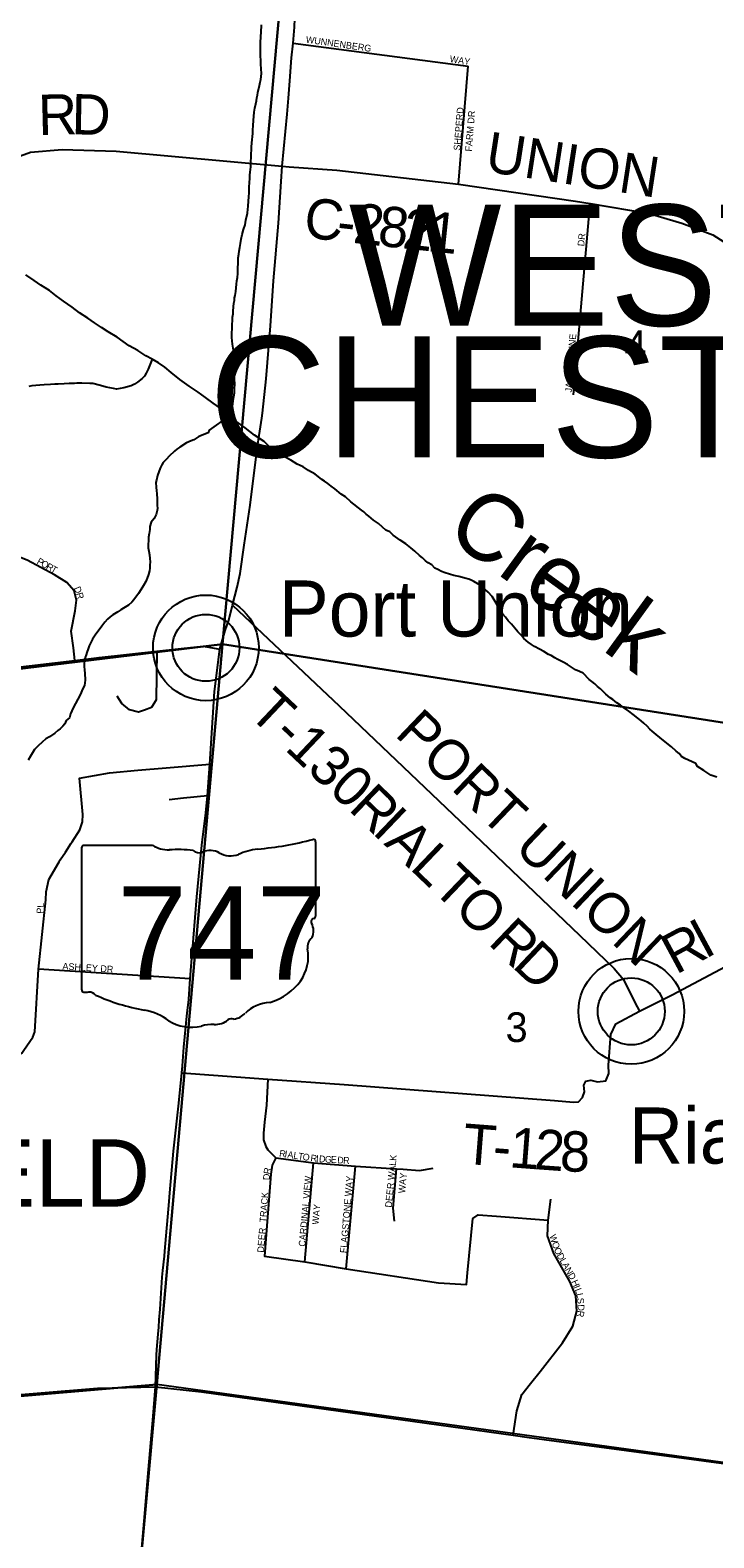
# Model space of a CAD drawing. Extents: x 1310247 to 1552180, y 377264 to 706493.
# Drawn here: x 1411903 to 1416988, y 484836 to 496050 of the extents above; entities that cross this region are included whole.
import ezdxf

# ---------------------------------------------------------------- set-up
doc = ezdxf.new("R2010")
doc.units = 0
for name, color, linetype in [('GM_X_City_Street', 7, 'Continuous'), ('GM_X_Corporation_Text', 7, 'Continuous'), ('GM_X_County_Road', 7, 'Continuous'), ('GM_X_County_Road_Text', 7, 'Continuous'), ('GM_X_Minor_River', 7, 'Continuous'), ('GM_X_Minor_River_Text', 7, 'Continuous'), ('GM_X_Section', 7, 'Continuous'), ('GM_X_Section_Text', 7, 'Continuous'), ('GM_X_State_Location', 7, 'Continuous'), ('GM_X_State_Route', 7, 'Continuous'), ('GM_X_State_Shield', 7, 'Continuous'), ('GM_X_Township_Road', 7, 'Continuous'), ('GM_X_Township_Road_Text', 7, 'Continuous'), ('GM_X_Township_Subdivision', 7, 'Continuous'), ('GM_X_Township_Subdivision_Text', 7, 'Continuous'), ('GM_X_Township_Text', 7, 'Continuous'), ('GM_X_Unincorporated', 7, 'Continuous'), ('GM_X_Unincorporated_Location', 7, 'Continuous'), ('GM_X_Unincorporated_Text', 7, 'Continuous')]:
    doc.layers.add(name, color=color, linetype=linetype)

msp = doc.modelspace()

# ---------------------------------------------------------------- linework, layer by layer
at = {"layer": 'GM_X_City_Street'}
msp.add_lwpolyline([(1413223, 490355), (1413043, 490337), (1412937, 490325)], dxfattribs=at)
at = {"layer": 'GM_X_County_Road'}
for points in [[(1408246, 494848), (1408977, 494429), (1409293, 494228), (1409610, 494093), (1409847, 494050), (1410120, 494057), (1410438, 494136), (1410670, 494255), (1410986, 494506), (1411392, 494848), (1411515, 494951), (1411672, 495059), (1411906, 495143), (1412141, 495163), (1412543, 495150), (1413777, 495038), (1413829, 495035)], [(1413829, 495035), (1414183, 495010), (1415090, 494905), (1415959, 494778), (1416068, 494762), (1416508, 494687), (1416751, 494616), (1416980, 494527), (1417280, 494338), (1417448, 494199), (1417669, 493954), (1417814, 493796), (1417927, 493690), (1418152, 493540), (1418294, 493471), (1418453, 493416), (1418749, 493371)], [(1407906, 490837), (1407912, 490836), (1408014, 490835), (1408238, 490860), (1408358, 490885), (1409402, 491011), (1410363, 491131), (1411747, 491305), (1412235, 491361), (1412416, 491385), (1412846, 491432), (1413026, 491451), (1413191, 491468), (1413313, 491445)], [(1408962, 485642), (1409118, 485655), (1409242, 485672), (1409576, 485698), (1410045, 485742), (1410812, 485814), (1411055, 485838), (1412404, 485949), (1412836, 485959)], [(1412836, 485959), (1413178, 485923), (1415496, 485599), (1415614, 485583), (1415727, 485567), (1417527, 485328), (1418095, 485240)]]:
    msp.add_lwpolyline(points, dxfattribs=at)
at = {"layer": 'GM_X_Minor_River'}
for points in [[(1413539, 494993), (1413544, 495035), (1413544, 495065), (1413547, 495111), (1413549, 495181), (1413551, 495213), (1413559, 495283), (1413559, 495308), (1413562, 495340), (1413565, 495380), (1413567, 495408), (1413570, 495440), (1413574, 495470), (1413581, 495502), (1413586, 495526), (1413590, 495548), (1413594, 495566), (1413597, 495586), (1413610, 495640), (1413614, 495664), (1413619, 495684), (1413624, 495728), (1413622, 495764), (1413619, 495798), (1413618, 495832), (1413616, 495853), (1413617, 495875), (1413616, 495929), (1413616, 495953), (1413619, 496005), (1413620, 496033), (1413623, 496091)], [(1413381, 493179), (1413410, 493268), (1413414, 493294), (1413419, 493326), (1413422, 493354), (1413424, 493376), (1413425, 493425), (1413423, 493449), (1413424, 493481), (1413427, 493509), (1413425, 493539), (1413425, 493611), (1413421, 493642), (1413412, 493686), (1413409, 493714), (1413404, 493764), (1413406, 493863), (1413408, 493889), (1413409, 493915), (1413412, 493941), (1413414, 493963), (1413419, 494021), (1413422, 494039), (1413424, 494059), (1413428, 494077), (1413433, 494107), (1413438, 494161), (1413440, 494185), (1413445, 494211), (1413448, 494240), (1413450, 494356), (1413455, 494384), (1413457, 494406), (1413462, 494434), (1413468, 494464), (1413473, 494496), (1413481, 494530), (1413490, 494568), (1413501, 494602), (1413508, 494638), (1413519, 494688), (1413523, 494720), (1413524, 494740), (1413526, 494780), (1413529, 494808), (1413532, 494844), (1413533, 494880), (1413535, 494920), (1413536, 494945), (1413538, 494973), (1413539, 494993)], [(1413720, 492916), (1413644, 492992), (1413571, 493037), (1413501, 493093), (1413449, 493129), (1413381, 493179), (1413330, 493229), (1413263, 493275), (1413208, 493317), (1413153, 493357), (1413086, 493403), (1413017, 493451), (1412951, 493503), (1412904, 493543), (1412857, 493576), (1412811, 493604), (1412764, 493627), (1412703, 493667), (1412640, 493703), (1412549, 493768), (1412482, 493807), (1412433, 493840), (1412382, 493874), (1412332, 493907), (1412271, 493949), (1412216, 493989), (1412152, 494035), (1412097, 494075), (1412046, 494115), (1411982, 494153), (1411933, 494189), (1411872, 494231)], [(1412811, 493604), (1412781, 493530), (1412766, 493499), (1412753, 493477), (1412737, 493460), (1412702, 493431), (1412679, 493417), (1412655, 493406), (1412628, 493397), (1412600, 493389), (1412572, 493384), (1412546, 493381), (1412522, 493384), (1412496, 493389), (1412468, 493396), (1412444, 493402), (1412416, 493409), (1412370, 493421), (1412348, 493423), (1412288, 493425), (1412250, 493424), (1412232, 493423), (1412194, 493422), (1412156, 493419), (1412111, 493418), (1412087, 493417), (1412055, 493414), (1412007, 493412), (1411975, 493409), (1411946, 493407), (1411916, 493404), (1411892, 493401)], [(1413381, 493179), (1413235, 493075), (1413227, 493055), (1413158, 493029), (1413121, 493004), (1413100, 492997), (1413066, 492980), (1413017, 492949), (1412994, 492934), (1412976, 492918), (1412936, 492881), (1412916, 492860), (1412893, 492835), (1412882, 492817), (1412870, 492793), (1412859, 492765), (1412850, 492738), (1412843, 492704), (1412838, 492686), (1412841, 492650), (1412843, 492625), (1412844, 492603), (1412847, 492563), (1412848, 492539), (1412847, 492515), (1412849, 492495), (1412848, 492477), (1412841, 492447), (1412826, 492417), (1412804, 492390), (1412793, 492358), (1412792, 492336), (1412787, 492306), (1412782, 492280), (1412780, 492200), (1412785, 492176), (1412790, 492147), (1412794, 492121), (1412795, 492095), (1412794, 492071), (1412794, 492049), (1412791, 492029), (1412782, 492001), (1412773, 491975), (1412763, 491949), (1412746, 491920), (1412725, 491888), (1412708, 491861), (1412674, 491814), (1412660, 491796), (1412635, 491773), (1412598, 491750), (1412578, 491738), (1412555, 491725), (1412518, 491702), (1412498, 491687), (1412479, 491669), (1412459, 491646), (1412436, 491616), (1412386, 491550), (1412367, 491520), (1412352, 491490), (1412343, 491471), (1412334, 491449), (1412324, 491421), (1412319, 491403), (1412312, 491385), (1412308, 491363), (1412305, 491341), (1412305, 491319), (1412306, 491291), (1412309, 491267), (1412311, 491215), (1412306, 491177), (1412291, 491143), (1412279, 491117), (1412257, 491074), (1412223, 491009), (1412202, 490965), (1412195, 490935), (1412172, 490916), (1412162, 490892), (1412147, 490874), (1412126, 490853), (1412108, 490840), (1412087, 490822), (1412046, 490795), (1412020, 490778), (1411993, 490755), (1411962, 490728), (1411935, 490700), (1411906, 490651), (1411889, 490621)], [(1416638, 490747), (1416587, 490789), (1416560, 490811), (1416530, 490836), (1416513, 490852), (1416491, 490873), (1416468, 490895), (1416448, 490914), (1416423, 490933), (1416389, 490959), (1416356, 490984), (1416316, 491013), (1416293, 491030), (1416267, 491048), (1416236, 491071), (1416218, 491085), (1416185, 491112), (1416144, 491151), (1416124, 491168), (1416102, 491188), (1416081, 491205), (1416061, 491221), (1416016, 491268), (1415989, 491281), (1415959, 491292), (1415921, 491316), (1415900, 491331), (1415868, 491350), (1415848, 491360), (1415823, 491373), (1415805, 491381), (1415777, 491398), (1415758, 491406), (1415724, 491429), (1415692, 491446), (1415655, 491465), (1415631, 491481), (1415606, 491498), (1415576, 491526), (1415557, 491547), (1415531, 491576), (1415508, 491602), (1415483, 491633), (1415459, 491657), (1415438, 491684), (1415418, 491706), (1415403, 491729), (1415382, 491767), (1415370, 491788), (1415339, 491837), (1415310, 491871), (1415290, 491888), (1415249, 491923), (1415204, 491950), (1415184, 491960), (1415166, 491967), (1415146, 491971), (1415091, 491986), (1415055, 491995), (1415023, 492004), (1414989, 492013), (1414962, 492025), (1414936, 492038), (1414914, 492048), (1414891, 492073), (1414863, 492088), (1414843, 492104), (1414820, 492125), (1414798, 492143), (1414763, 492176), (1414734, 492201), (1414698, 492229), (1414655, 492258), (1414621, 492281), (1414604, 492294), (1414578, 492318), (1414549, 492331), (1414523, 492354), (1414494, 492382), (1414456, 492405), (1414421, 492436), (1414403, 492450), (1414386, 492467), (1414368, 492481), (1414346, 492498), (1414311, 492525), (1414289, 492543), (1414248, 492578), (1414217, 492599), (1414170, 492638), (1414142, 492659), (1414116, 492679), (1414093, 492696), (1414073, 492708), (1414046, 492731), (1414022, 492748), (1413973, 492775), (1413933, 492802), (1413890, 492821), (1413841, 492852), (1413720, 492916)], [(1417011, 490495), (1416965, 490508), (1416914, 490543), (1416867, 490574), (1416855, 490596), (1416772, 490632), (1416748, 490649), (1416729, 490669), (1416709, 490688), (1416672, 490719), (1416638, 490747)]]:
    msp.add_lwpolyline(points, dxfattribs=at)
at = {"layer": 'GM_X_Section'}
for points in [[(1413822, 496918), (1413333, 491483), (1407877, 490818), (1408326, 496083)], [(1419005, 496045), (1418523, 490671), (1413333, 491483), (1413822, 496918)], [(1407877, 490818), (1413333, 491483), (1412844, 485977), (1407418, 485512)], [(1413333, 491483), (1418523, 490671), (1418027, 485262), (1412844, 485977)], [(1412844, 485977), (1412356, 480589), (1406968, 480262), (1407418, 485512)]]:
    msp.add_lwpolyline(points, close=True, dxfattribs=at)
at = {"layer": 'GM_X_State_Route'}
for points in [[(1413824, 495545), (1413834, 495674), (1413846, 495845), (1413858, 495953), (1413869, 496073), (1413877, 496267), (1413880, 496383), (1413881, 496480), (1413877, 496694), (1413870, 496923)], [(1413625, 493165), (1413631, 493201), (1413659, 493457), (1413690, 493852), (1413714, 494187), (1413751, 494615), (1413769, 494924), (1413777, 495038), (1413814, 495426), (1413824, 495545)], [(1413098, 489055), (1413117, 489297), (1413142, 489603), (1413180, 489988), (1413210, 490228), (1413223, 490355), (1413240, 490591), (1413275, 491131), (1413313, 491445), (1413354, 491584), (1413381, 491662), (1413409, 491774), (1413442, 491907), (1413464, 492010), (1413495, 492219), (1413539, 492517), (1413573, 492798), (1413596, 492970), (1413625, 493165)], [(1413082, 488843), (1413093, 488993), (1413098, 489055)], [(1413035, 488346), (1413047, 488485), (1413070, 488742), (1413080, 488817), (1413082, 488843)], [(1412942, 487403), (1412970, 487711), (1413008, 488070), (1413031, 488296), (1413035, 488346)], [(1412901, 486930), (1412905, 486969), (1412936, 487339), (1412942, 487403)], [(1412863, 486457), (1412871, 486538), (1412885, 486774), (1412890, 486825)], [(1412890, 486825), (1412901, 486930)], [(1412854, 486352), (1412859, 486404)], [(1412859, 486404), (1412863, 486457)], [(1412843, 486194), (1412844, 486237), (1412854, 486352)], [(1412671, 484038), (1412679, 484127), (1412691, 484269), (1412714, 484545), (1412721, 484619), (1412752, 484960), (1412784, 485344), (1412817, 485742), (1412836, 485959), (1412843, 486194)]]:
    msp.add_lwpolyline(points, dxfattribs=at)
at = {"layer": 'GM_X_State_Shield'}
for p, q in [((1412286, 489969), (1412286, 488912)), ((1412813, 489987), (1412304, 489987)), ((1414027, 489461), (1414027, 490013)), ((1414026, 489461), (1414027, 489461))]:
    msp.add_line(p, q, dxfattribs=at)
for centre, major_axis, start_param, end_param in [((1412306, 489971), (20.2, 0), 1.712693, 3.28349), ((1412935, 490110), (196, 0), 4.042523, 4.731795), ((1413407, 491428), (1845, 0), 4.814394, 5.042369), ((1414007, 490016), (19.4, 0), 6.141152, 7.989035), ((1412999, 489394), (702, 0), 1.404758, 1.657858), ((1413159, 489977), (56.4, 0), 3.836095, 5.185415), ((1413242, 489855), (117, 0), 0.950623, 2.079405), ((1413393, 490022), (141, 0), 4.081561, 5.145723), ((1413642, 489664), (371, 0), 1.699011, 2.107814), ((1414022, 489420), (30, 0), 1.883978, 3.671073), ((1413831, 489350), (180, 0), 5.934695, 6.695948), ((1414006, 489458), (20.7, 0), 5.05454, 6.418171), ((1414096, 489229), (131, 0), 2.387724, 3.262537), ((1413510, 489159), (462, 0), 5.101752, 6.440018), ((1412307, 488910), (20.3, 0), 3.00124, 4.508301), ((1412310, 489018), (155, 0), 4.665946, 4.897461), ((1412341, 488851), (56, 0), 0.519207, 1.627899), ((1413048, 489801), (1333, 0), 4.195997, 4.488961), ((1412651, 488438), (417, 0), 0.823519, 1.323587), ((1413384, 488810), (149, 0), 4.937069, 5.64225), ((1413705, 488616), (253, 0), 1.647645, 2.488434), ((1413102, 488846), (265, 0), 4.026481, 4.996735), ((1413255, 488481), (217, 0), 1.495662, 1.94098), ((1413274, 488767), (141, 0), 4.691044, 5.507374), ((1413401, 488665), (39.7, 0), 1.147584, 2.315152)]:
    msp.add_ellipse(centre, major_axis=major_axis, ratio=0.8, start_param=start_param, end_param=end_param, dxfattribs=at)
at = {"layer": 'GM_X_Township_Road'}
for points in [[(1413409, 491774), (1414201, 491025), (1415259, 490016), (1415990, 489320), (1416246, 489070), (1416316, 488989), (1416400, 488819), (1416436, 488753)], [(1416436, 488753), (1416678, 488874), (1417430, 489275), (1417774, 489463), (1418255, 489749), (1418329, 489815), (1418416, 489943), (1418459, 490096), (1418473, 490280), (1418513, 490647)], [(1413031, 488296), (1413671, 488247), (1414239, 488208), (1415804, 488088), (1415944, 488076), (1415982, 488078), (1416012, 488112), (1416026, 488153), (1416021, 488202), (1416036, 488233), (1416074, 488241), (1416123, 488229), (1416185, 488236), (1416207, 488290), (1416204, 488352), (1416223, 488580), (1416259, 488659), (1416436, 488753)]]:
    msp.add_lwpolyline(points, dxfattribs=at)
at = {"layer": 'GM_X_Township_Subdivision'}
for points in [[(1413858, 495953), (1415160, 495782)], [(1415090, 494905), (1415160, 495782)], [(1415944, 493338), (1416068, 494762)], [(1412235, 491361), (1412226, 491456), (1412209, 491580), (1412237, 491731), (1412247, 491810), (1412231, 491880), (1412177, 491941), (1412084, 491998), (1411880, 492107), (1411625, 492208), (1411531, 492219)], [(1412846, 491432), (1412840, 491069), (1412805, 491013), (1412754, 490993), (1412709, 490978), (1412642, 490994), (1412586, 491041), (1412549, 491097)], [(1412215, 490013), (1412273, 490102), (1412292, 490163), (1412295, 490216), (1412271, 490486), (1412492, 490526), (1412703, 490547), (1412915, 490564), (1413240, 490591)], [(1410018, 488199), (1410616, 488298), (1411541, 488380), (1411732, 488403), (1411813, 488421), (1411841, 488442), (1411856, 488463), (1411923, 488560), (1411939, 488600), (1411964, 489067), (1412019, 489581), (1412022, 489640), (1412041, 489733), (1412120, 489865), (1412126, 489880), (1412167, 489936), (1412209, 490003), (1412215, 490013)], [(1413093, 488993), (1411964, 489067)], [(1413671, 488247), (1413661, 488054), (1413647, 487929), (1413639, 487847), (1413638, 487796), (1413656, 487748), (1413670, 487722), (1413730, 487663), (1414011, 487626), (1414322, 487601), (1414629, 487581), (1414677, 487578), (1414798, 487569), (1414900, 487586)], [(1413730, 487663), (1413704, 487609), (1413693, 487541), (1413645, 486932), (1413947, 486888), (1414253, 486836), (1414939, 486734), (1415148, 486721), (1415156, 486806), (1415196, 487212), (1415236, 487239), (1415371, 487229), (1415756, 487198)], [(1413947, 486888), (1414011, 487626)], [(1414253, 486836), (1414322, 487601)], [(1414614, 487191), (1414602, 487289), (1414629, 487581)], [(1415696, 486074), (1415863, 486286), (1415939, 486410), (1415969, 486521), (1415962, 486637), (1415917, 486743), (1415799, 486952), (1415752, 487083), (1415756, 487198), (1415775, 487354)], [(1415496, 485599), (1415523, 485780), (1415560, 485903), (1415624, 485984), (1415696, 486074)]]:
    msp.add_lwpolyline(points, dxfattribs=at)
at = {"layer": 'GM_X_Unincorporated'}
for centre, radius in [((1413210, 491456), 393), ((1413210, 491456), 249), ((1416374, 488752), 393), ((1416374, 488752), 249)]:
    msp.add_circle(centre, radius, dxfattribs=at)
at = {"layer": 'GM_X_Unincorporated_Location'}
for p, q in [((1413210, 491456), (1413210, 491456)), ((1416374, 488752), (1416374, 488752))]:
    msp.add_line(p, q, dxfattribs=at)

# ---------------------------------------------------------------- texts
at = {"layer": 'GM_X_Corporation_Text'}
msp.add_text('FAIRFIELD', height=500, rotation=0, dxfattribs=at).set_placement((1409377, 487300))
at = {"layer": 'GM_X_County_Road_Text'}
for s, rotation, p in [('R', 1.4228, (1411966, 495270)), ('D', 358.8032, (1412209, 495276)), ('UNION', 351.2378, (1415279, 495001)), ('C', 353.6702, (1413930, 494510)), ('2', 353.6746, (1414298, 494469)), ('8', 353.6928, (1414481, 494449)), ('2', 353.7588, (1414665, 494429)), ('1', 353.9991, (1414850, 494408)), ('-', 353.6684, (1414175, 494483))]:
    msp.add_text(s, height=300, rotation=rotation, dxfattribs=at).set_placement(p)
at = {"layer": 'GM_X_Minor_River_Text'}
msp.add_text('Creek', height=500, rotation=324.0162, dxfattribs=at).set_placement((1414974, 492297))
at = {"layer": 'GM_X_Section_Text'}
for s, p in [('4', (1416324, 493597)), ('3', (1415439, 488524))]:
    msp.add_text(s, height=221, rotation=0, dxfattribs=at).set_placement(p)
at = {"layer": 'GM_X_State_Location'}
msp.add_text('747', height=1, rotation=0, dxfattribs=at).set_placement((1412784, 489298))
for s in ['s', 'r']:
    msp.add_text(s, height=1, dxfattribs=at).set_placement((1413137, 489370))
at = {"layer": 'GM_X_State_Shield'}
msp.add_text('747', height=696.1, dxfattribs=at).set_placement((1412552, 488987))
at = {"layer": 'GM_X_Township_Road_Text'}
for s, rotation, p in [('T-130', 316.5908, (1413515, 490962)), ('PORT UNION', 316.2871, (1414608, 490807)), ('R', 316.2227, (1414263, 490253)), ('I', 316.2199, (1414440, 490082)), ('A', 316.2244, (1414529, 489997)), ('L', 316.2213, (1414720, 489815)), ('T', 316.2245, (1414882, 489659)), ('O', 316.2236, (1415044, 489504)), ('R', 316.266, (1415302, 489257)), ('I', 28.3319, (1416922, 489139)), ('R', 28.33, (1416706, 489022)), ('D', 316.5791, (1415481, 489086)), ('T', 355.5492, (1415113, 487620)), ('1', 355.6388, (1415461, 487593)), ('2', 355.915, (1415646, 487579)), ('8', 357.3997, (1415839, 487565)), ('-', 355.5666, (1415337, 487603))]:
    msp.add_text(s, height=300, rotation=rotation, dxfattribs=at).set_placement(p)
at = {"layer": 'GM_X_Township_Subdivision_Text'}
for s, rotation, p in [('WUNNENBERG', 351.8688, (1413951, 495958)), ('WAY', 351.1207, (1415021, 495813)), ('SHEPERD', 85.3901, (1415102, 495153)), ('FARM DR', 85.3901, (1415188, 495146)), ('DR', 83.994, (1416023, 494441)), ('JACQUEMINE', 85.4519, (1415931, 493354)), ('P', 330.6601, (1411948, 492085)), ('O', 330.6681, (1411979, 492068)), ('R', 330.6773, (1412017, 492046)), ('T', 330.9324, (1412052, 492027)), ('D', 292.4711, (1412227, 491900)), ('R', 285.6886, (1412244, 491860)), ('PL', 86.4254, (1412000, 489477)), ('ASHLEY DR', 356.3328, (1412142, 489064)), ('R', 351.3582, (1413753, 487673)), ('I', 351.3403, (1413793, 487667)), ('A', 351.3579, (1413814, 487664)), ('L', 351.3483, (1413858, 487657)), ('T', 351.3645, (1413893, 487652)), ('O', 351.3552, (1413927, 487647)), ('R', 353.1293, (1413986, 487638)), ('I', 355.9421, (1414028, 487633)), ('D', 356.3278, (1414050, 487631)), ('G', 356.3673, (1414094, 487628)), ('E', 356.364, (1414138, 487626)), ('D', 356.3673, (1414186, 487622)), ('R', 356.3669, (1414230, 487620)), ('DEER WALK', 84.4268, (1414592, 487291)), ('D', 88.1746, (1413685, 487496)), ('R', 79.9308, (1413687, 487538)), ('CARDINAL VIEW', 84.852, (1413949, 487000)), ('FLAGSTONE WAY', 85.1568, (1414257, 486952)), ('WAY', 84.8053, (1414691, 487397)), ('TRACK', 85.9841, (1413659, 487180)), ('WAY', 84.805, (1414048, 487164)), ('DEER', 85.2358, (1413641, 486956)), ('W', 288.2462, (1415764, 487083)), ('O', 288.6409, (1415782, 487029)), ('O', 292.4204, (1415797, 486983)), ('D', 299.6999, (1415817, 486937)), ('L', 299.8181, (1415839, 486898)), ('A', 299.8234, (1415857, 486868)), ('N', 299.8234, (1415878, 486830)), ('D', 299.1809, (1415900, 486791)), ('H', 293.411, (1415927, 486742)), ('I', 292.2113, (1415944, 486702)), ('L', 291.1444, (1415953, 486682)), ('L', 281.3983, (1415965, 486651)), ('S', 274.5674, (1415971, 486619)), ('R', 261.0886, (1415977, 486529)), ('D', 272.7003, (1415975, 486571))]:
    msp.add_text(s, height=50, rotation=rotation, dxfattribs=at).set_placement(p)
at = {"layer": 'GM_X_Township_Text'}
for s, p in [('WEST', (1414273, 493852)), ('CHESTER', (1413235, 492872))]:
    msp.add_text(s, height=900, rotation=0, dxfattribs=at).set_placement(p)
at = {"layer": 'GM_X_Unincorporated_Text'}
for s, p in [('Port Union', (1413752, 491540)), ('Rialto', (1416357, 487620))]:
    msp.add_text(s, height=417, rotation=0, dxfattribs=at).set_placement(p)

doc.saveas('drawing.dxf')
